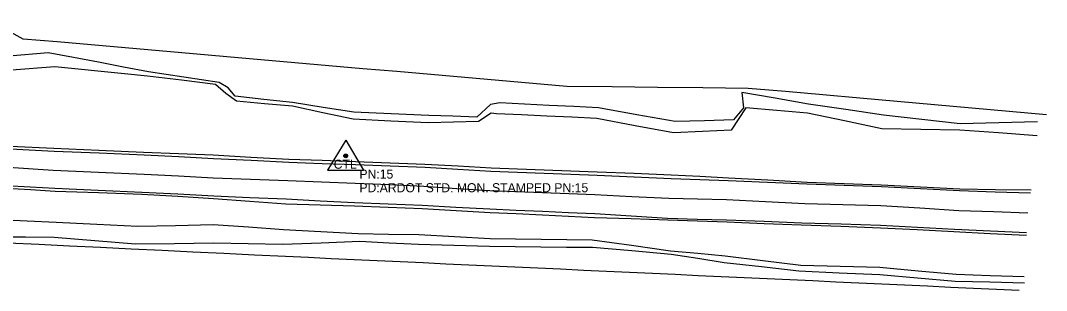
# Model space of a CAD drawing. Extents: x 1138803 to 1169983, y 1655906 to 1658226.
# Drawn here: x 1165485 to 1166048, y 1656650 to 1656798 of the extents above; entities that cross this region are included whole.
import ezdxf

# ---------------------------------------------------------------- set-up
doc = ezdxf.new("R2010")
doc.units = 0
for name, color, linetype in [('S_DITCHLINE', 7, 'Continuous'), ('S_EDGE_PAVEMENT', 7, 'Continuous'), ('S_PAVEMENT_CROWN', 7, 'Continuous'), ('S_PRIMARY_CTL', 7, 'Continuous'), ('S_PRIMARY_CTL_ANNOT', 7, 'Continuous'), ('S_SHOULDER', 7, 'Continuous'), ('S_TREE', 7, 'Continuous')]:
    doc.layers.add(name, color=color, linetype=linetype)

msp = doc.modelspace()

# ---------------------------------------------------------------- linework, layer by layer
at = {"layer": 'S_DITCHLINE'}
for points in [[(1166043.02, 1656742.75), (1166021.82, 1656742.23), (1166000.62, 1656741.71), (1165979.53, 1656744.05), (1165958.44, 1656746.38), (1165937.83, 1656749.46), (1165917.22, 1656752.53), (1165898.96, 1656755.73), (1165880.71, 1656758.94), (1165881.64, 1656750.42), (1165876.15, 1656743.78), (1165860.15, 1656743.33), (1165844.14, 1656742.89), (1165823.1, 1656746.66), (1165802.06, 1656750.43), (1165788.52, 1656751.11), (1165774.97, 1656751.8), (1165761.43, 1656752.48), (1165747.89, 1656753.16), (1165742.8, 1656752.31), (1165735.23, 1656745.34), (1165722.1, 1656745.79), (1165708.96, 1656746.23), (1165688.34, 1656747.15), (1165667.71, 1656748.07), (1165650.95, 1656750.7), (1165634.19, 1656753.32), (1165618.45, 1656755.1), (1165602.71, 1656756.87), (1165598.71, 1656761.39), (1165593.8, 1656764.28), (1165574.48, 1656767.24), (1165555.16, 1656770.2), (1165541.39, 1656772.83), (1165527.62, 1656775.46), (1165513.84, 1656778.09), (1165500.07, 1656780.72), (1165478.62, 1656778.89)], [(1166042.82, 1656735.01), (1166021.55, 1656736.62), (1166000.29, 1656738.23), (1165978.88, 1656738.54), (1165957.47, 1656738.85), (1165937.13, 1656743.2), (1165916.78, 1656747.56), (1165899.89, 1656748.96), (1165882.99, 1656750.36), (1165874.81, 1656738.16), (1165859.04, 1656737.39), (1165843.26, 1656736.62), (1165822.21, 1656740.6), (1165801.15, 1656744.59), (1165787.38, 1656745.22), (1165773.61, 1656745.86), (1165759.84, 1656746.5), (1165746.06, 1656747.13), (1165743.07, 1656747.55), (1165736.11, 1656742.85), (1165722.39, 1656742.48), (1165708.66, 1656742.1), (1165687.99, 1656743.11), (1165667.32, 1656744.12), (1165650.75, 1656747.7), (1165634.19, 1656751.27), (1165618.81, 1656752.65), (1165603.43, 1656754.02), (1165597.51, 1656758.28), (1165591.88, 1656763.27), (1165573.23, 1656765.58), (1165554.58, 1656767.89), (1165541.86, 1656769.16), (1165529.15, 1656770.43), (1165516.44, 1656771.69), (1165503.73, 1656772.96), (1165480.09, 1656771.15)], [(1166035.67, 1656657.42), (1166017, 1656658.07), (1165998.33, 1656658.73), (1165977.4, 1656660.66), (1165956.48, 1656662.59), (1165934.76, 1656663.18), (1165913.04, 1656663.77), (1165892.28, 1656666.34), (1165871.52, 1656668.92), (1165856.53, 1656670.28), (1165841.55, 1656671.65), (1165820.09, 1656674.68), (1165798.63, 1656677.71), (1165784.61, 1656677.89), (1165770.6, 1656678.07), (1165756.58, 1656678.25), (1165742.56, 1656678.43), (1165722.98, 1656679.5), (1165703.41, 1656680.56), (1165686.78, 1656680.87), (1165670.15, 1656681.17), (1165649.67, 1656682.28), (1165629.19, 1656683.39), (1165609.88, 1656684.75), (1165590.57, 1656686.12), (1165569.93, 1656685.64), (1165549.28, 1656685.16), (1165526.8, 1656686.23), (1165504.32, 1656687.3), (1165488.53, 1656688.11), (1165472.74, 1656688.92)], [(1166035.88, 1656654.05), (1166016.85, 1656654.49), (1165997.81, 1656654.93), (1165977.15, 1656656.73), (1165956.48, 1656658.54), (1165934.21, 1656659.57), (1165911.93, 1656660.61), (1165891.48, 1656662.95), (1165871.03, 1656665.29), (1165856.49, 1656667.57), (1165841.95, 1656669.86), (1165820.32, 1656671.72), (1165798.69, 1656673.57), (1165784.56, 1656673.73), (1165770.44, 1656673.89), (1165756.31, 1656674.04), (1165742.19, 1656674.2), (1165722.72, 1656674.74), (1165703.26, 1656675.27), (1165687.17, 1656676.08), (1165671.08, 1656676.88), (1165649.81, 1656676.07), (1165628.54, 1656675.26), (1165609.72, 1656675.65), (1165590.91, 1656676.05), (1165569.43, 1656675.74), (1165547.94, 1656675.43), (1165525.6, 1656677.29), (1165503.26, 1656679.15), (1165487.49, 1656679.27), (1165471.72, 1656679.39)]]:
    msp.add_lwpolyline(points, dxfattribs=at)
at = {"layer": 'S_EDGE_PAVEMENT'}
for points in [[(1166039.18, 1656703.51), (1166019.71, 1656704.12), (1166000.24, 1656704.74), (1165978.75, 1656705.9), (1165957.27, 1656707.07), (1165936.82, 1656707.75), (1165916.38, 1656708.43), (1165894.79, 1656709.35), (1165873.2, 1656710.27), (1165857.59, 1656710.83), (1165841.98, 1656711.39), (1165821.69, 1656712.3), (1165801.4, 1656713.21), (1165786.77, 1656713.78), (1165772.14, 1656714.36), (1165757.52, 1656714.93), (1165742.89, 1656715.5), (1165724.87, 1656716.57), (1165706.85, 1656717.65), (1165687.75, 1656718.34), (1165668.65, 1656719.04), (1165650.39, 1656719.72), (1165632.14, 1656720.41), (1165611.48, 1656721.43), (1165590.82, 1656722.45), (1165571.72, 1656723.44), (1165552.62, 1656724.43), (1165528, 1656725.46), (1165503.38, 1656726.49), (1165479.25, 1656727.75)], [(1166036.94, 1656681.64), (1166017.18, 1656682.61), (1165997.42, 1656683.59), (1165977.15, 1656684.67), (1165956.89, 1656685.75), (1165935.24, 1656686.43), (1165913.59, 1656687.1), (1165892.93, 1656687.85), (1165872.26, 1656688.6), (1165856.11, 1656689.08), (1165839.97, 1656689.56), (1165819.98, 1656690.83), (1165800, 1656692.11), (1165785.61, 1656692.75), (1165771.22, 1656693.39), (1165756.83, 1656694.03), (1165742.44, 1656694.67), (1165723.82, 1656695.69), (1165705.2, 1656696.71), (1165686.66, 1656697.42), (1165668.11, 1656698.14), (1165649.36, 1656699.14), (1165630.61, 1656700.15), (1165610.76, 1656701.03), (1165590.91, 1656701.91), (1165571.17, 1656702.88), (1165551.42, 1656703.86), (1165527.52, 1656704.99), (1165503.62, 1656706.11), (1165490.18, 1656706.86), (1165476.74, 1656707.61)]]:
    msp.add_lwpolyline(points, dxfattribs=at)
at = {"layer": 'S_PAVEMENT_CROWN'}
msp.add_lwpolyline([(1166037.74, 1656692.47), (1166018.78, 1656693.16), (1165999.81, 1656693.85), (1165978.36, 1656695.21), (1165956.9, 1656696.57), (1165936.12, 1656697.07), (1165915.33, 1656697.58), (1165893.76, 1656698.68), (1165872.2, 1656699.79), (1165856.46, 1656700.16), (1165840.72, 1656700.53), (1165820.42, 1656701.59), (1165800.12, 1656702.65), (1165785.68, 1656703.17), (1165771.24, 1656703.68), (1165756.8, 1656704.2), (1165742.36, 1656704.71), (1165724.27, 1656705.96), (1165706.19, 1656707.2), (1165687.32, 1656708.02), (1165668.46, 1656708.84), (1165650.01, 1656709.61), (1165631.56, 1656710.38), (1165611.04, 1656711.05), (1165590.51, 1656711.73), (1165571.57, 1656712.78), (1165552.62, 1656713.84), (1165527.69, 1656714.94), (1165502.76, 1656716.03), (1165478.31, 1656717.59)], dxfattribs=at)
at = {"layer": 'S_PRIMARY_CTL'}
for p, q in [((1165663.32, 1656732.71), (1165653.29, 1656716.2)), ((1165663.32, 1656732.71), (1165673.14, 1656716.2)), ((1165653.29, 1656716.2), (1165673.14, 1656716.2))]:
    msp.add_line(p, q, dxfattribs=at)
for radius in [1.04, 0.609, 0.344]:
    msp.add_circle((1165663.32, 1656724.01), radius, dxfattribs=at)
at = {"layer": 'S_SHOULDER'}
for points in [[(1166039.48, 1656705.11), (1166019.95, 1656705.43), (1166000.42, 1656705.74), (1165978.78, 1656706.83), (1165957.14, 1656707.93), (1165936.86, 1656708.7), (1165916.58, 1656709.46), (1165895.01, 1656710.65), (1165873.45, 1656711.84), (1165857.73, 1656712.64), (1165842.01, 1656713.45), (1165821.66, 1656714.25), (1165801.31, 1656715.05), (1165786.76, 1656715.61), (1165772.22, 1656716.17), (1165757.68, 1656716.74), (1165743.13, 1656717.3), (1165724.96, 1656718.29), (1165706.8, 1656719.28), (1165687.78, 1656720.03), (1165668.76, 1656720.77), (1165650.41, 1656721.41), (1165632.07, 1656722.05), (1165611.31, 1656723.2), (1165590.56, 1656724.35), (1165571.49, 1656725.08), (1165552.41, 1656725.81), (1165527.77, 1656726.98), (1165503.13, 1656728.14), (1165479.15, 1656729.24)], [(1166036.95, 1656680.26), (1166017.04, 1656681.23), (1165997.13, 1656682.19), (1165977, 1656683.27), (1165956.86, 1656684.35), (1165935.08, 1656685.12), (1165913.29, 1656685.89), (1165892.99, 1656686.68), (1165872.69, 1656687.48), (1165856.42, 1656688.06), (1165840.14, 1656688.63), (1165820, 1656689.33), (1165799.86, 1656690.04), (1165785.55, 1656690.71), (1165771.24, 1656691.39), (1165756.93, 1656692.07), (1165742.62, 1656692.75), (1165723.92, 1656693.82), (1165705.23, 1656694.89), (1165686.68, 1656695.65), (1165668.14, 1656696.4), (1165649.3, 1656696.98), (1165630.46, 1656697.55), (1165610.62, 1656699.02), (1165590.78, 1656700.48), (1165571.14, 1656701.6), (1165551.49, 1656702.71), (1165527.7, 1656703.61), (1165503.91, 1656704.51), (1165490.37, 1656705.28), (1165476.83, 1656706.06)]]:
    msp.add_lwpolyline(points, dxfattribs=at)
at = {"layer": 'S_TREE'}
for points in [[(1166047.9, 1656746.63), (1166027.43, 1656748.44), (1166006.96, 1656750.26), (1165986.49, 1656752.07), (1165966.02, 1656753.89), (1165945.55, 1656755.7), (1165925.08, 1656757.52), (1165904.61, 1656759.33), (1165884.13, 1656761.15), (1165859.26, 1656761.41), (1165834.39, 1656761.67), (1165809.51, 1656761.93), (1165784.64, 1656762.19), (1165765.99, 1656763.82), (1165747.34, 1656765.45), (1165728.69, 1656767.08), (1165710.04, 1656768.71), (1165691.39, 1656770.34), (1165672.74, 1656771.97), (1165654.09, 1656773.6), (1165635.44, 1656775.23), (1165616.79, 1656776.86), (1165598.14, 1656778.49), (1165579.5, 1656780.12), (1165560.85, 1656781.76), (1165542.2, 1656783.39), (1165523.55, 1656785.02), (1165504.9, 1656786.65), (1165486.25, 1656788.28), (1165467.68, 1656798.47)], [(1166032.97, 1656649.98), (1166020.38, 1656650.57), (1166007.8, 1656651.15), (1165995.21, 1656651.73), (1165982.63, 1656652.32), (1165970.04, 1656652.9), (1165957.46, 1656653.48), (1165944.87, 1656654.07), (1165932.29, 1656654.65), (1165919.7, 1656655.23), (1165907.12, 1656655.82), (1165894.53, 1656656.4), (1165881.95, 1656656.98), (1165869.36, 1656657.57), (1165856.78, 1656658.15), (1165844.19, 1656658.73), (1165831.61, 1656659.31), (1165819.02, 1656659.9), (1165806.44, 1656660.48), (1165793.85, 1656661.06), (1165781.27, 1656661.65), (1165768.68, 1656662.23), (1165756.1, 1656662.81), (1165743.51, 1656663.4), (1165730.93, 1656663.98), (1165718.34, 1656664.56), (1165705.76, 1656665.15), (1165693.17, 1656665.73), (1165680.58, 1656666.31), (1165668, 1656666.9), (1165655.41, 1656667.48), (1165642.83, 1656668.06), (1165630.24, 1656668.64), (1165613.32, 1656669.46), (1165596.39, 1656670.28), (1165579.47, 1656671.11), (1165562.55, 1656671.93), (1165545.62, 1656672.75), (1165528.7, 1656673.57), (1165511.77, 1656674.39), (1165494.85, 1656675.21), (1165477.92, 1656676.03)]]:
    msp.add_lwpolyline(points, dxfattribs=at)

# ---------------------------------------------------------------- texts
at = {"layer": 'S_PRIMARY_CTL'}
msp.add_text('CTL', height=5, rotation=360, dxfattribs=at).set_placement((1165656.73, 1656716.94))
at = {"layer": 'S_PRIMARY_CTL_ANNOT'}
for s, p in [('PN:15', (1165670.82, 1656711.51)), ('PD:ARDOT STD. MON. STAMPED PN:15', (1165670.82, 1656704.01))]:
    msp.add_text(s, height=5, dxfattribs=at).set_placement(p)

doc.saveas('drawing.dxf')
